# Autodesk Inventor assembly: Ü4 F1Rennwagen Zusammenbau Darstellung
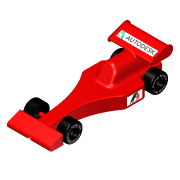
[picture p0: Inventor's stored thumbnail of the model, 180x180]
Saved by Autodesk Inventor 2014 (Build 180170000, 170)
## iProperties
Created: 2013-07
Part Number: Ü4 F1Rennwagen Zusammenbau Darstellung
Document SubType Name: Assembly
Designer: Sofia
Author: Sofia
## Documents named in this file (5)
- C:\F1 in Schools\Workspace\Ü4 F1Rennwagen Zusammenbau Darstellung.iam
- C:\F1 in Schools\Workspace\Rad.ipt
- C:\F1 in Schools\Workspace\Sicherungsring.ipt
- C:\F1 in Schools\Workspace\Achse.ipt
- C:\F1 in Schools\Workspace\Ü4 F1 Karosserie Darstellung komplett.ipt
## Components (9 placed, 4 different names)
1. Ü4 F1 Karosserie Darstellung komplett:1 — Passend:1, Passend:2, Einfügen:1, Passend:3, Passend:4
2. Achse:1 — Einfügen:2, Passend:3, Einfügen:3
3. Sicherungsring:1 — Einfügen:2, Einfügen:4
4. Rad:1 — Passend:1, Passend:2, Einfügen:3
5. Achse:2 — Passend:4, Einfügen:5, Einfügen:6
6. Sicherungsring:2 — Einfügen:6, Einfügen:7
7. Rad:2 — Einfügen:7
8. Rad:3 — Einfügen:4
9. Rad:4 — Einfügen:1, Einfügen:5
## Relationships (11: Insert 7, Mate 4)
- Passend:1 [Mate]: Ü4 F1 Karosserie Darstellung komplett:1 ↔ Rad:1
- Passend:2 [Mate]: Ü4 F1 Karosserie Darstellung komplett:1 ↔ Rad:1
- Einfügen:1 [Insert]: Ü4 F1 Karosserie Darstellung komplett:1 ↔ Rad:4
- Einfügen:2 [Insert]: Achse:1 ↔ Sicherungsring:1
- Passend:3 [Mate]: Ü4 F1 Karosserie Darstellung komplett:1 ↔ Achse:1
- Einfügen:3 [Insert]: Achse:1 ↔ Rad:1
- Einfügen:4 [Insert]: Sicherungsring:1 ↔ Rad:3
- Passend:4 [Mate]: Ü4 F1 Karosserie Darstellung komplett:1 ↔ Achse:2
- Einfügen:5 [Insert]: Achse:2 ↔ Rad:4
- Einfügen:6 [Insert]: Achse:2 ↔ Sicherungsring:2
- Einfügen:7 [Insert]: Sicherungsring:2 ↔ Rad:2
